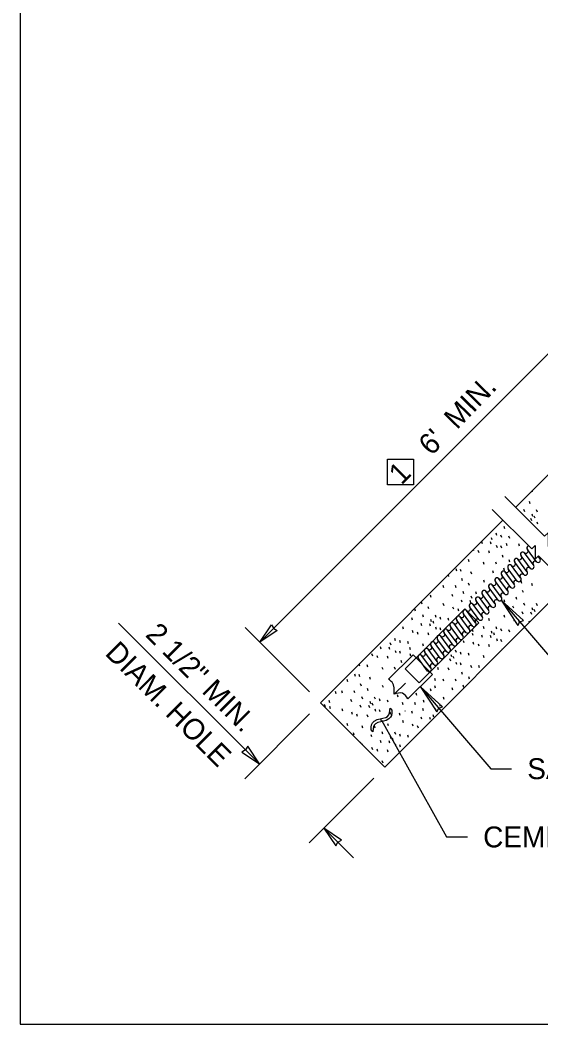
# Model space of a CAD drawing. Extents: x 99861 to 103151, y 100000 to 102076.
# Drawn here: x 99861 to 100260, y 100000 to 100768 of the extents above; entities that cross this region are included whole.
import ezdxf

# ---------------------------------------------------------------- set-up
doc = ezdxf.new("R2010")
doc.units = 0
for name, color, linetype in [('Level 1', 7, 'Continuous'), ('Level 15', 7, 'Continuous'), ('Level 2', 7, 'Continuous'), ('Level 20', 7, 'Continuous'), ('Level 60', 7, 'Continuous'), ('Level 8', 7, 'Continuous')]:
    doc.layers.add(name, color=color, linetype=linetype)

# ---------------------------------------------------------------- blocks, each defined once
blk = doc.blocks.new('T')
at = {"layer": 'Level 15'}
blk.add_lwpolyline([(0, 0), (-22.829, 2.985), (-21.773, 0), (-22.83, -2.985)], close=True, dxfattribs=at)

msp = doc.modelspace()

# ---------------------------------------------------------------- linework, layer by layer
at = {"layer": 'Level 1'}
for p, q in [((100251.39, 100348.95), (100244.46, 100358.4)), ((100253.85, 100351.41), (100246.92, 100360.86)), ((100256.3, 100353.86), (100249.37, 100363.31)), ((100258.76, 100356.32), (100257.49, 100358.05)), ((100244.02, 100341.57), (100237.09, 100351.03)), ((100246.48, 100344.04), (100239.55, 100353.49)), ((100248.94, 100346.49), (100242, 100355.94)), ((100236.65, 100334.2), (100229.72, 100343.65)), ((100239.11, 100336.66), (100232.18, 100346.11)), ((100241.57, 100339.12), (100234.63, 100348.56)), ((100229.28, 100326.83), (100222.35, 100336.28)), ((100231.74, 100329.29), (100224.81, 100338.74)), ((100234.2, 100331.75), (100227.26, 100341.2)), ((100221.92, 100319.45), (100214.98, 100328.9)), ((100224.37, 100321.91), (100217.44, 100331.36)), ((100226.82, 100324.37), (100219.9, 100333.83)), ((100214.54, 100312.09), (100207.61, 100321.53)), ((100217, 100314.54), (100210.07, 100323.99)), ((100219.46, 100317), (100212.53, 100326.44)), ((100207.18, 100304.7), (100200.25, 100314.15)), ((100209.63, 100307.16), (100202.7, 100316.62)), ((100212.09, 100309.63), (100205.15, 100319.07)), ((100197.36, 100294.88), (100190.43, 100304.33)), ((100199.81, 100297.33), (100192.88, 100306.78)), ((100202.26, 100299.79), (100195.33, 100309.24)), ((100204.72, 100302.25), (100197.8, 100311.7)), ((100180.43, 100297.34), (100180.19, 100297.04)), ((100189.99, 100287.5), (100183.06, 100296.95)), ((100192.44, 100289.96), (100185.51, 100299.41)), ((100194.89, 100292.42), (100187.96, 100301.87)), ((100182.61, 100280.13), (100175.69, 100289.58)), ((100185.07, 100282.59), (100178.14, 100292.03)), ((100187.52, 100285.04), (100180.6, 100294.49)), ((100175.25, 100272.75), (100168.32, 100282.21)), ((100177.7, 100275.21), (100170.78, 100284.66)), ((100180.15, 100277.67), (100173.22, 100287.11)), ((100172.79, 100270.29), (100165.86, 100279.74))]:
    msp.add_line(p, q, dxfattribs=at)
msp.add_lwpolyline([(99861, 100000), (103150, 100000), (103150, 102076), (99861, 102076)], close=True, dxfattribs=at)
for centre, start, end in [((100250.6, 100364.54), 112.05081, 225.01905), ((100243.23, 100357.17), 225.01905, 45.01866), ((100245.69, 100359.63), 45.01866, 225.01905), ((100248.15, 100362.09), 225.01905, 45.01866), ((100259.99, 100357.55), 170.05696, 225.01905), ((100235.86, 100349.8), 45.01866, 225.01905), ((100238.32, 100352.25), 225.01905, 45.01866), ((100240.78, 100354.71), 45.01866, 225.01905), ((100252.62, 100350.18), 225.01905, 45.01866), ((100255.08, 100352.64), 45.01866, 225.01905), ((100257.53, 100355.09), 225.01905, 45.01866), ((100228.49, 100342.42), 225.01905, 45.01866), ((100230.95, 100344.88), 45.01866, 225.01905), ((100233.41, 100347.34), 225.01905, 45.01866), ((100245.25, 100342.8), 45.01866, 225.01905), ((100247.71, 100345.26), 225.01905, 45.01866), ((100250.16, 100347.72), 45.01866, 225.01905), ((100221.13, 100335.05), 45.01866, 225.01905), ((100223.58, 100337.51), 225.01905, 45.01866), ((100226.04, 100339.96), 45.01866, 225.01905), ((100237.88, 100335.43), 225.01905, 45.01866), ((100240.34, 100337.89), 45.01866, 225.01905), ((100242.8, 100340.35), 225.01905, 45.01866), ((100213.76, 100327.67), 225.01905, 45.01866), ((100216.21, 100330.13), 45.01866, 225.01905), ((100218.67, 100332.59), 225.01905, 45.01866), ((100230.51, 100328.06), 45.01866, 225.01905), ((100232.97, 100330.51), 225.01905, 45.01866), ((100235.43, 100332.97), 45.01866, 225.01905), ((100206.39, 100320.3), 45.01866, 225.01905), ((100208.84, 100322.76), 225.01905, 45.01866), ((100211.3, 100325.22), 45.01866, 225.01905), ((100220.69, 100318.22), 45.01866, 225.01905), ((100223.15, 100320.68), 225.01905, 45.01866), ((100225.6, 100323.14), 45.01866, 225.01905), ((100228.06, 100325.6), 225.01905, 45.01866), ((100196.56, 100310.47), 45.01866, 225.01905), ((100199.02, 100312.93), 225.01905, 45.01866), ((100201.48, 100315.38), 45.01866, 225.01905), ((100203.93, 100317.84), 225.01905, 45.01866), ((100213.32, 100310.85), 225.01905, 45.01866), ((100215.78, 100313.31), 45.01866, 225.01905), ((100218.23, 100315.77), 225.01905, 45.01866), ((100189.19, 100303.09), 225.01905, 45.01866), ((100191.65, 100305.55), 45.01866, 225.01905), ((100194.11, 100308.01), 225.01905, 45.01866), ((100205.95, 100303.48), 45.01866, 225.01905), ((100208.41, 100305.94), 225.01905, 45.01866), ((100210.86, 100308.39), 45.01866, 225.01905), ((100181.83, 100295.72), 45.01866, 225.01905), ((100184.28, 100298.18), 225.01905, 45.01866), ((100186.74, 100300.64), 45.01866, 225.01905), ((100198.58, 100296.1), 225.01905, 45.01866), ((100201.04, 100298.56), 45.01866, 225.01905), ((100203.5, 100301.02), 225.01905, 45.01866), ((100174.46, 100288.35), 225.01905, 45.01866), ((100176.91, 100290.81), 45.01866, 225.01905), ((100174.46, 100288.35), 325.00054, 45.01866), ((100179.37, 100293.26), 225.01905, 45.01866), ((100191.21, 100288.73), 45.01866, 225.01905), ((100193.67, 100291.19), 225.01905, 45.01866), ((100196.13, 100293.65), 45.01866, 225.01905), ((100167.09, 100280.97), 45.01866, 225.01905), ((100169.54, 100283.43), 225.01905, 45.01866), ((100169.54, 100283.43), 225.01905, 12.15897), ((100172, 100285.89), 45.01866, 225.01905), ((100183.84, 100281.36), 225.01905, 45.01866), ((100183.84, 100281.36), 261.88875, 45.01866), ((100186.3, 100283.81), 45.01866, 225.01905), ((100188.76, 100286.27), 225.01905, 45.01866), ((100176.48, 100273.98), 45.01866, 225.01905), ((100178.93, 100276.44), 225.01905, 45.01866), ((100178.93, 100276.44), 225.01905, 307.3566), ((100181.38, 100278.9), 45.01866, 225.01905), ((100174.02, 100271.52), 225.01905, 45.01866)]:
    msp.add_arc(centre, 1.74, start, end, dxfattribs=at)
at = {"layer": 'Level 15'}
for p, q in [((100370.21, 100618.21), (100044.49, 100292.32)), ((100229.29, 100324.37), (100283.19, 100261.59)), ((100033.2, 100303.61), (100082.44, 100254.39)), ((100167.29, 100258.33), (100221.19, 100195.55)), ((100137.63, 100232.79), (100187.45, 100143.33)), ((100221.19, 100195.55), (100237.19, 100195.55)), ((100187.45, 100143.33), (100203.45, 100143.33))]:
    msp.add_line(p, q, dxfattribs=at)
for points in [[(100232.12, 100403.88), (100262.49, 100373.51), (100265.12, 100376.14), (100265.12, 100365.62), (100267.75, 100368.25), (100298.73, 100337.26)], [(100222.4, 100393.85), (100252.59, 100363.66), (100255.22, 100366.28), (100255.22, 100355.77), (100257.84, 100358.4), (100289.49, 100326.75)]]:
    msp.add_lwpolyline(points, dxfattribs=at)
for points in [[(100229.29, 100324.37), (100241.89, 100305.1), (100243.47, 100307.85), (100246.42, 100308.99)], [(100044.49, 100292.32), (100053.42, 100305.62), (100055.09, 100302.93), (100057.79, 100301.26)], [(100167.29, 100258.33), (100179.89, 100239.07), (100181.47, 100241.81), (100184.42, 100242.96)]]:
    msp.add_lwpolyline(points, close=True, dxfattribs=at)
at = {"layer": 'Level 2'}
for p, q in [((100155.64, 100271.92), (100201.48, 100317.8)), ((100201.48, 100317.8), (100212.21, 100307.08)), ((100212.21, 100307.08), (100166.37, 100261.2)), ((100142.91, 100263.97), (100161.74, 100282.59)), ((100161.74, 100282.59), (100176.7, 100267.64)), ((100166.37, 100261.2), (100155.64, 100271.92)), ((100176.7, 100267.64), (100157.87, 100249.02)), ((100155.97, 100261.09), (100147.26, 100252.48)), ((100178.96, 100262.82), (100178.39, 100264.56)), ((100102.93, 100252.81), (100102.36, 100254.55)), ((100150.31, 100250.38), (100149.74, 100252.13)), ((100140.17, 100196.7), (100090.93, 100245.91))]:
    msp.add_line(p, q, dxfattribs=at)
for points in [[(100240.46, 100395.54), (100414.92, 100569.98)], [(100279.81, 100336.43), (100140.17, 100196.7), (100090.93, 100245.91), (100230.59, 100385.66)]]:
    msp.add_lwpolyline(points, dxfattribs=at)
for points in [[(100147.26, 100252.48), (100145.72, 100261.63), (100142.91, 100263.97)], [(100157.87, 100249.02), (100153.62, 100253.32), (100147.26, 100252.48)]]:
    msp.add_spline(points, degree=3, dxfattribs=at)
at = {"layer": 'Level 20'}
for p, q in [((100044.27, 100199.23), (99936.43, 100307)), ((100082.44, 100237.42), (100032.96, 100187.91)), ((100140.94, 100234.82), (100142.24, 100235.57)), ((100142.24, 100235.57), (100143.16, 100236.66)), ((100143.16, 100236.66), (100143.79, 100238.18)), ((100144.41, 100234.89), (100143.26, 100233.68)), ((100143.79, 100238.18), (100144.18, 100241.85)), ((100144.18, 100241.85), (100145.52, 100240.22)), ((100145.14, 100236.33), (100144.41, 100234.89)), ((100145.51, 100238.07), (100145.14, 100236.33)), ((100145.52, 100240.22), (100145.51, 100238.07)), ((100129.6, 100227.26), (100129.95, 100229.02)), ((100129.67, 100225.27), (100129.6, 100227.26)), ((100129.95, 100229.02), (100130.73, 100230.53)), ((100130.73, 100230.53), (100131.94, 100231.82)), ((100131.48, 100227.76), (100131.13, 100226.06)), ((100132.1, 100228.97), (100131.48, 100227.76)), ((100131.94, 100231.82), (100134.31, 100233.15)), ((100133, 100229.95), (100132.1, 100228.97)), ((100134.69, 100230.87), (100133, 100229.95)), ((100134.31, 100233.15), (100138.59, 100234.23)), ((100137.16, 100231.51), (100134.69, 100230.87)), ((100141.14, 100232.43), (100137.16, 100231.51)), ((100138.59, 100234.23), (100140.94, 100234.82)), ((100143.26, 100233.68), (100141.14, 100232.43)), ((100131.01, 100223.64), (100129.67, 100225.27)), ((100131.13, 100226.06), (100131.01, 100223.64)), ((100032.95, 100210.54), (100044.27, 100199.23)), ((100131.69, 100188.21), (100082.21, 100138.7)), ((100116.15, 100127.4), (100093.51, 100150.02))]:
    msp.add_line(p, q, dxfattribs=at)
msp.add_lwpolyline([(100142.3, 100432.49), (100162.16, 100432.49), (100162.16, 100412.63), (100142.3, 100412.63)], close=True, dxfattribs=at)
at = {"layer": 'Level 60'}
msp.add_line((99862, 99999.5), (99862, 99999.5), dxfattribs=at)
at = {"layer": 'Level 8'}
for p, q in [((100253.15, 100407.05), (100252.86, 100407.94)), ((100251.37, 100398.29), (100250.8, 100400.03)), ((100247.2, 100392.01), (100246.63, 100393.76)), ((100253.42, 100388.44), (100252.85, 100390.19)), ((100255.1, 100387.14), (100254.52, 100388.89)), ((100256.92, 100391.82), (100256.34, 100393.56)), ((100252.57, 100385.22), (100252, 100386.97)), ((100257.31, 100382.54), (100256.74, 100384.29)), ((100225.92, 100373.92), (100225.35, 100375.67)), ((100229.61, 100372.43), (100229.04, 100374.17)), ((100231.99, 100379.09), (100231.42, 100380.84)), ((100235.75, 100371.64), (100235.18, 100373.39)), ((100214.95, 100367.59), (100214.38, 100369.33)), ((100221.58, 100367.33), (100221, 100369.08)), ((100222.42, 100370.55), (100221.85, 100372.3)), ((100226.31, 100364.65), (100225.74, 100366.4)), ((100229.59, 100364.22), (100229.02, 100365.96)), ((100233.89, 100366), (100233.32, 100367.74)), ((100243.21, 100365.75), (100242.64, 100367.5)), ((100208.36, 100362.24), (100208.07, 100363.13)), ((100212.28, 100360.81), (100211.71, 100362.55)), ((100220.27, 100360.38), (100219.69, 100362.13)), ((100230.67, 100357.11), (100230.1, 100358.85)), ((100204.75, 100353.75), (100204.18, 100355.49)), ((100216.27, 100351.89), (100215.7, 100353.63)), ((100225.73, 100351.93), (100225.16, 100353.68)), ((100235.88, 100353.54), (100235.31, 100355.28)), ((100189.27, 100342.49), (100188.82, 100343.87)), ((100195.32, 100346.75), (100194.75, 100348.5)), ((100198.59, 100346.32), (100198.02, 100348.07)), ((100206.66, 100344.41), (100206.09, 100346.15)), ((100223.28, 100345.1), (100222.71, 100346.85)), ((100231.71, 100347.26), (100231.14, 100349.01)), ((100185.28, 100333.99), (100184.71, 100335.74)), ((100194.73, 100334.03), (100194.16, 100335.78)), ((100199.67, 100339.21), (100199.1, 100340.96)), ((100204.88, 100335.64), (100204.31, 100337.39)), ((100216.5, 100338.09), (100215.93, 100339.84)), ((100245.09, 100337.36), (100244.52, 100339.11)), ((100253.16, 100335.44), (100252.59, 100337.19)), ((100175.67, 100326.51), (100175.1, 100328.26)), ((100192.29, 100327.21), (100191.72, 100328.95)), ((100200.72, 100329.37), (100200.14, 100331.11)), ((100206.93, 100325.8), (100206.36, 100327.54)), ((100210.43, 100329.17), (100209.86, 100330.92)), ((100246.18, 100330.25), (100245.6, 100332)), ((100168.68, 100321.32), (100168.11, 100323.06)), ((100173.89, 100317.75), (100173.32, 100319.49)), ((100185.51, 100320.2), (100184.93, 100321.94)), ((100199.46, 100322.84), (100198.89, 100324.58)), ((100206.09, 100322.58), (100205.51, 100324.32)), ((100232.01, 100322.89), (100231.44, 100324.64)), ((100238.79, 100318.25), (100238.22, 100319.99)), ((100241.23, 100325.07), (100240.66, 100326.82)), ((100247.22, 100320.4), (100246.65, 100322.15)), ((100256.93, 100320.21), (100256.36, 100321.96)), ((100163.74, 100316.14), (100163.17, 100317.89)), ((100169.72, 100311.47), (100169.15, 100313.22)), ((100179.44, 100311.28), (100178.86, 100313.02)), ((100192.87, 100317.49), (100192.3, 100319.23)), ((100196.8, 100316.05), (100196.22, 100317.8)), ((100232.01, 100311.24), (100231.43, 100312.98)), ((100245.96, 100313.87), (100245.39, 100315.62)), ((100252.59, 100313.62), (100252.01, 100315.36)), ((100253.43, 100316.84), (100252.86, 100318.58)), ((100255.11, 100315.53), (100254.54, 100317.28)), ((100154.51, 100302.3), (100153.94, 100304.05)), ((100161.29, 100309.31), (100160.72, 100311.06)), ((100168.46, 100304.94), (100167.89, 100306.69)), ((100175.09, 100304.68), (100174.52, 100306.43)), ((100175.94, 100307.9), (100175.37, 100309.65)), ((100177.62, 100306.6), (100177.04, 100308.35)), ((100183.13, 100309.78), (100182.56, 100311.53)), ((100189.26, 100309), (100188.69, 100310.74)), ((100216.22, 100302.51), (100215.65, 100304.26)), ((100220.39, 100308.78), (100219.82, 100310.53)), ((100225.94, 100302.31), (100225.37, 100304.06)), ((100239.37, 100308.53), (100238.8, 100310.27)), ((100243.3, 100307.09), (100242.72, 100308.84)), ((100250.98, 100307.58), (100250.71, 100308.42)), ((100161.88, 100299.59), (100161.31, 100301.34)), ((100165.8, 100298.16), (100165.23, 100299.91)), ((100173.78, 100297.74), (100173.21, 100299.48)), ((100179.83, 100302), (100179.26, 100303.75)), ((100183.1, 100301.57), (100182.53, 100303.32)), ((100207.79, 100300.35), (100207.22, 100302.1)), ((100207.79, 100297.36), (100207.22, 100299.1)), ((100214.96, 100295.98), (100214.39, 100297.73)), ((100221.59, 100295.72), (100221.02, 100297.47)), ((100222.44, 100298.94), (100221.87, 100300.69)), ((100224.12, 100297.64), (100223.54, 100299.38)), ((100229.63, 100300.82), (100229.06, 100302.57)), ((100235.76, 100300.04), (100235.19, 100301.78)), ((100137.47, 100287.05), (100136.9, 100288.79)), ((100138.73, 100293.58), (100138.68, 100293.7)), ((100144.94, 100290.01), (100144.37, 100291.75)), ((100148.44, 100293.38), (100147.87, 100295.13)), ((100152.13, 100291.89), (100151.56, 100293.63)), ((100158.27, 100291.1), (100157.7, 100292.85)), ((100169.79, 100289.24), (100169.22, 100290.99)), ((100201.01, 100291.74), (100200.44, 100293.48)), ((100208.38, 100290.63), (100207.81, 100292.38)), ((100212.3, 100289.2), (100211.73, 100290.94)), ((100220.28, 100288.78), (100219.71, 100290.52)), ((100226.33, 100293.04), (100225.76, 100294.79)), ((100229.6, 100292.61), (100229.03, 100294.36)), ((100130.88, 100281.7), (100130.31, 100283.44)), ((100134.81, 100280.26), (100134.23, 100282.01)), ((100142.79, 100279.84), (100142.21, 100281.59)), ((100144.1, 100286.79), (100143.52, 100288.53)), ((100148.83, 100284.11), (100148.26, 100285.85)), ((100152.11, 100283.68), (100151.54, 100285.42)), ((100159.8, 100286.45), (100159.23, 100288.2)), ((100160.18, 100281.76), (100159.61, 100283.51)), ((100191.44, 100281.05), (100190.87, 100282.79)), ((100193.12, 100279.74), (100192.55, 100281.49)), ((100194.94, 100284.42), (100194.37, 100286.17)), ((100198.63, 100282.93), (100198.06, 100284.67)), ((100204.77, 100282.14), (100204.2, 100283.89)), ((100216.29, 100280.28), (100215.72, 100282.03)), ((100225.25, 100281.83), (100225.17, 100282.07)), ((100230.25, 100286.84), (100230.11, 100287.24)), ((100121.14, 100273.99), (100120.61, 100275.61)), ((100127.27, 100273.21), (100126.7, 100274.95)), ((100153.19, 100276.56), (100152.62, 100278.31)), ((100190.6, 100277.83), (100190.02, 100279.57)), ((100195.34, 100275.15), (100194.76, 100276.89)), ((100198.61, 100274.72), (100198.04, 100276.46)), ((100206.68, 100272.8), (100206.11, 100274.54)), ((100212.63, 100272.83), (100212.06, 100274.58)), ((100117.84, 100266.21), (100117.27, 100267.96)), ((100121.11, 100265.78), (100120.54, 100267.53)), ((100129.18, 100263.86), (100128.61, 100265.61)), ((100138.79, 100271.35), (100138.22, 100273.09)), ((100148.25, 100271.39), (100147.68, 100273.13)), ((100181.31, 100271.3), (100180.73, 100273.05)), ((100189.29, 100270.88), (100188.72, 100272.63)), ((100199.69, 100267.6), (100199.12, 100269.35)), ((100204.9, 100264.03), (100204.33, 100265.78)), ((100111.79, 100261.95), (100111.22, 100263.69)), ((100122.2, 100258.67), (100121.62, 100260.42)), ((100139.02, 100257.55), (100138.45, 100259.3)), ((100179.03, 100257.15), (100178.45, 100258.9)), ((100185.29, 100262.39), (100184.72, 100264.13)), ((100194.75, 100262.43), (100194.18, 100264.17)), ((100200.73, 100257.76), (100200.16, 100259.5)), ((100107.8, 100253.45), (100107.23, 100255.2)), ((100117.25, 100253.49), (100116.68, 100255.24)), ((100123.24, 100248.82), (100122.67, 100250.57)), ((100127.4, 100255.1), (100126.83, 100256.85)), ((100132.95, 100248.63), (100132.38, 100250.38)), ((100164.64, 100251.54), (100164.07, 100253.28)), ((100175.69, 100254.9), (100175.11, 100256.65)), ((100185.52, 100248.59), (100184.95, 100250.34)), ((100192.31, 100255.6), (100191.73, 100257.35)), ((100094.69, 100242.8), (100094.11, 100244.55)), ((100098.19, 100245.97), (100097.62, 100247.72)), ((100098.61, 100241.37), (100098.04, 100243.11)), ((100114.81, 100246.67), (100114.24, 100248.41)), ((100121.98, 100242.29), (100121.41, 100244.04)), ((100128.61, 100242.04), (100128.03, 100243.78)), ((100129.45, 100245.26), (100128.88, 100247)), ((100131.13, 100243.95), (100130.56, 100245.7)), ((100136.64, 100247.14), (100136.07, 100248.88)), ((100142.78, 100246.35), (100142.21, 100248.1)), ((100154.3, 100244.49), (100153.73, 100246.24)), ((100163.75, 100244.53), (100163.18, 100246.28)), ((100170.32, 100246.14), (100169.75, 100247.88)), ((100182.88, 100243.24), (100182.31, 100244.99)), ((100108.03, 100239.66), (100107.45, 100241.4)), ((100115.39, 100236.95), (100114.82, 100238.69)), ((100119.32, 100235.51), (100118.74, 100237.26)), ((100127.3, 100235.09), (100126.73, 100236.84)), ((100133.34, 100239.36), (100132.77, 100241.1)), ((100136.62, 100238.93), (100136.05, 100240.67)), ((100144.69, 100237.01), (100144.12, 100238.75)), ((100151.9, 100236.3), (100151.33, 100238.04)), ((100155.86, 100239.33), (100155.66, 100239.92)), ((100161.31, 100237.71), (100160.74, 100239.45)), ((100168.48, 100233.33), (100167.91, 100235.08)), ((100169.74, 100239.86), (100169.17, 100241.61)), ((100177.63, 100234.99), (100177.06, 100236.74)), ((100179.45, 100239.67), (100178.88, 100241.41)), ((100111.78, 100228.46), (100111.21, 100230.2)), ((100123.3, 100226.6), (100122.73, 100228.34)), ((100132.76, 100226.64), (100132.19, 100228.38)), ((100137.7, 100231.81), (100137.13, 100233.56)), ((100142.91, 100228.24), (100142.34, 100229.99)), ((100154.53, 100230.69), (100153.95, 100232.44)), ((100161.89, 100227.98), (100161.32, 100229.73)), ((100165.82, 100226.55), (100165.24, 100228.3)), ((100175.11, 100233.08), (100174.54, 100234.82)), ((100116.77, 100221.29), (100116.2, 100223.04)), ((100130.32, 100219.81), (100129.74, 100221.56)), ((100138.74, 100221.97), (100138.17, 100223.71)), ((100144.96, 100218.4), (100144.39, 100220.15)), ((100148.46, 100221.77), (100147.89, 100223.52)), ((100152.15, 100220.28), (100151.58, 100222.03)), ((100158.28, 100219.49), (100157.71, 100221.24)), ((100121.77, 100215.09), (100121.52, 100215.84)), ((100123.27, 100213.58), (100122.96, 100214.55)), ((100130.9, 100210.09), (100130.33, 100211.84)), ((100137.48, 100215.44), (100136.91, 100217.18)), ((100144.11, 100215.18), (100143.54, 100216.93)), ((100146.64, 100217.1), (100146.07, 100218.84)), ((100148.85, 100212.5), (100148.28, 100214.25)), ((100152.12, 100212.07), (100151.55, 100213.82)), ((100134.82, 100208.66), (100134.25, 100210.4)), ((100142.8, 100208.23), (100142.23, 100209.98)), ((100138.81, 100199.74), (100138.24, 100201.49))]:
    msp.add_line(p, q, dxfattribs=at)

# ---------------------------------------------------------------- block references
at = {"layer": 'Level 20', "xscale": 0.700832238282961}
for p, yscale, rotation in [((100044.27, 100199.23), 1.0720268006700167, -44.98115163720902), ((100093.51, 100150.02), 1.072026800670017, 135.01884836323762)]:
    msp.add_blockref('T', p, dxfattribs=dict(at, yscale=yscale, rotation=rotation))

# ---------------------------------------------------------------- texts
at = {"layer": 'Level 20'}
for s, rotation, p in [("6'  MIN.", 45.81137, (100175.92, 100434.41)), ('1', 45, (100152.91, 100412.12)), ('2 1/2" MIN.', 315.01885, (99956.22, 100297.44)), ('DIAM. HOLE ', 315.01885, (99925.23, 100283.17))]:
    msp.add_text(s, height=16, rotation=rotation, dxfattribs=at).set_placement(p)
for s, p in [('SACRIFICIAL DRILL BIT', (100249.19, 100187.55)), ('CEMENT GROUT', (100215.45, 100135.33))]:
    msp.add_text(s, height=16, dxfattribs=at).set_placement(p)

doc.saveas('drawing.dxf')
